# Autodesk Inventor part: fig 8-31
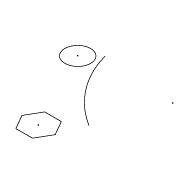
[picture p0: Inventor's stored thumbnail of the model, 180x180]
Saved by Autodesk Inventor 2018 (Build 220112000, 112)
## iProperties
Shininess: 77.0
Angle Display Precision: 2
Document Length Units: 11269
Document Angle Units: 11279
Document Time Units: 11290
Document Mass Units: 11283
Document Length Units Precision: 3
Document Angle Units Precision: 2
Created: 2001-12
Part Number: fig 8-31
Document SubType Name: Modeling
Designer: CADSoft
Density: 1 g/cm^3
Material: Generic
Appearance: Default
Density: 0.0
Volumn: 0.0
Area: 0.0
PropertySet Name: Model Information
Control State: 0
Master: False
Checked Out: False
Author: CADSoft
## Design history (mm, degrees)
workplane "Work Plane3"
workplane "Work Plane4"
sketch "Sketch12"
  geometry: L1 (0, 10.598)-(9.178, -5.299); L2 (9.178, -5.299)-(-9.178, -5.299); L3 (-9.178, -5.299)-(0, 10.598); 1 further point
  constraints: 6 end point, 5 other
workplane "Work Plane5"
workplane "Work Plane6"
workplane "Work Plane7"
sketch "Sketch16"
  geometry: A1 r 72.799 centre (23.007, 110.594) between (0, 41.527) and (70, 54.995); 1 further point
  constraints: 2 point on circle, 1 centre point
body "Solid1"
sketch "Sketch1"
  geometry: L1 (19.387, 0)-(9.693, -16.79); L2 (9.693, -16.79)-(-9.693, -16.79); L3 (-9.693, -16.79)-(-19.387, 0); L4 (-19.387, 0)-(-9.693, 16.79); L5 (-9.693, 16.79)-(9.693, 16.79); L6 (9.693, 16.79)-(19.387, 0); 1 further point
  constraints: 12 end point, 11 other
sketch "Sketch2"
  geometry: C1 r 15 at (23.06, 22.535)
  constraints: 1 centre point
